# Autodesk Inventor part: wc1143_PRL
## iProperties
Shininess: 64.0
Length Units: 11272
Angle Units: 11279
Time Units: 11290
Mass Units: 11286
Length Display Precision: 3
Angle Display Precision: 2
Compacted: True
Part Number: wc1143_PRL
Document SubType Name: Modeling
Created: 2004-08
Designer: John Blackburn
Manufacturer: Standard
Standards Organization: Custom
Material: Lexan, Clear
Density: 0.0
Volumn: 0.0
Area: 0.0
PropertySet Name: Model Information
Control State: 0
Master: False
Checked Out: False
Author: John Blackburn
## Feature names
1. Revolution1
